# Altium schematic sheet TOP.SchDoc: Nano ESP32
size A3; Author: Silvio Navaretti; Revision: V0.3; SheetNumber: 1; SheetTotal: 1; RevAuthor: Silvio Navaretti
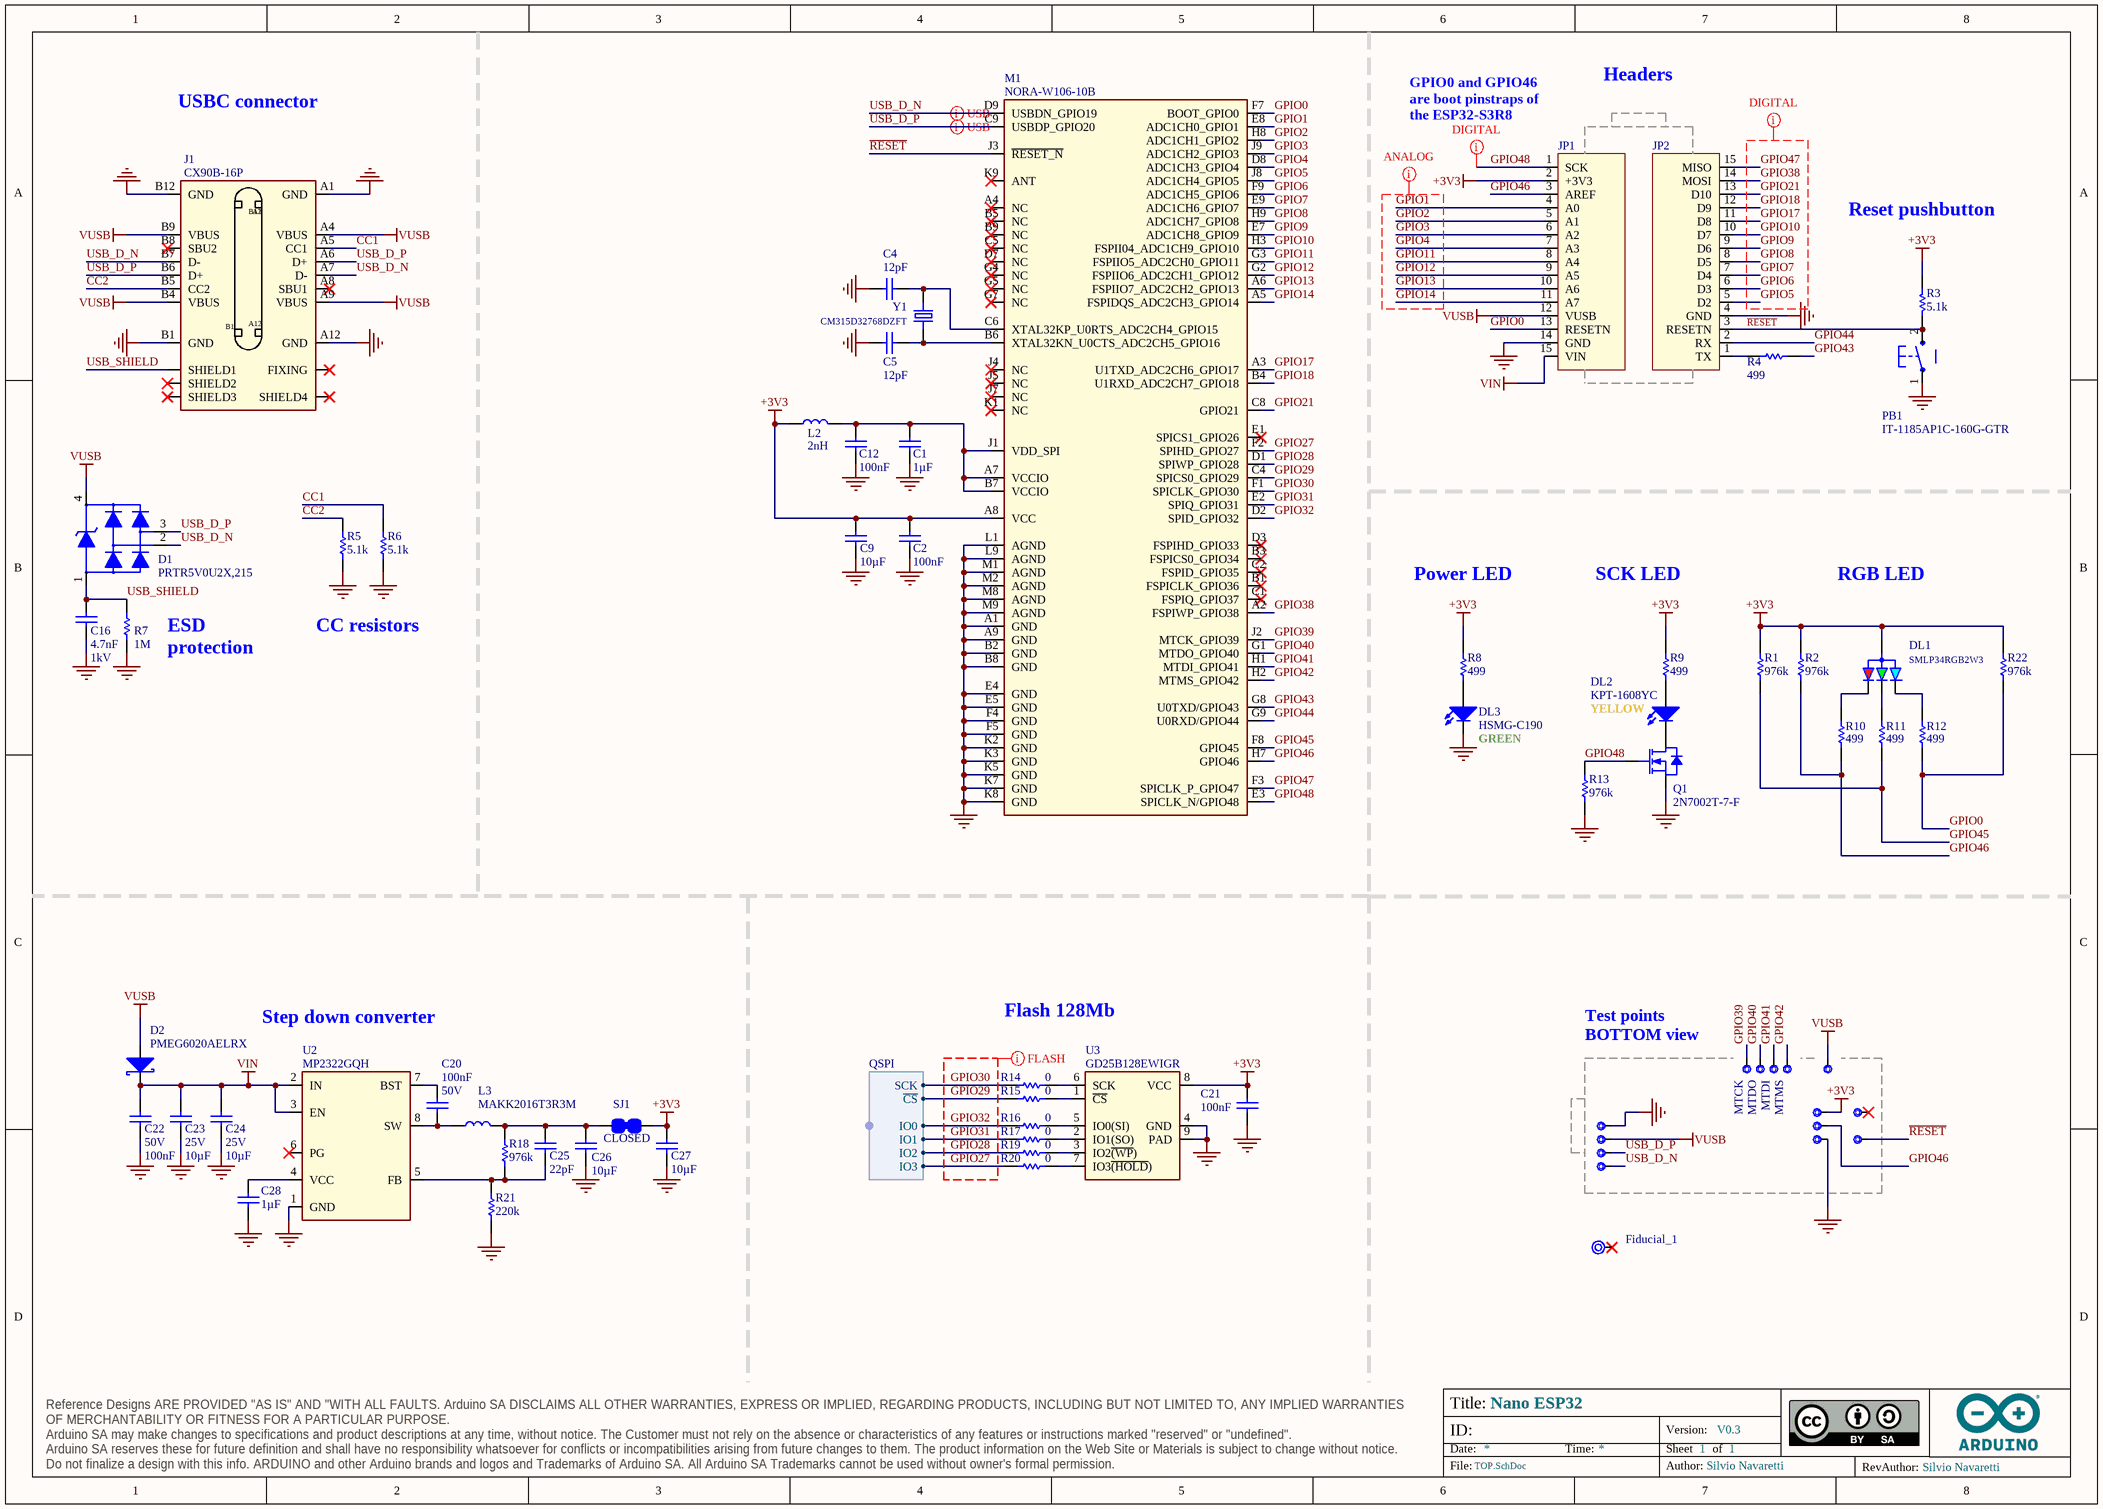
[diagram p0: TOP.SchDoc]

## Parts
3V3  CMP-018-0005-A.3  [TP-1.00MM]  (value not drawn)  (no BOM)
C1  value 1µF  [CAP-0201]  (hidden comment: GRM033R60J105MEA2D)
C2  value 100nF  [CAP-0402]  (hidden comment: GRM155R61H104KE19D)
C4  value 12pF  [CAP-0201]  (hidden comment: GRM0335C1E120JA01J)
C5  value 12pF  [CAP-0201]  (hidden comment: GRM0335C1E120JA01J)
C9  value 10µF  [CAP-0603]  (hidden comment: GRM188R61E106MA73J)
C12  value 100nF  [CAP-0402]  (hidden comment: GRM155R61H104KE19D)
C16  value 4.7nF  Voltage: 1kV  [CAP-0805]  (hidden comment: C0805C472KDRACTU)
C20  value 100nF  Voltage: 50V  [CAP-0402]  (hidden comment: GRM155R61H104KE19D)
C21  value 100nF  [CAP-0402]  (hidden comment: GRM155R61H104KE19D)
C22  value 100nF  Voltage: 50V  [CAP-0402]  (hidden comment: GRM155R61H104KE19D)
C23  value 10µF  Voltage: 25V  [CAP-0603]  (hidden comment: GRM188R61E106MA73J)
C24  value 10µF  Voltage: 25V  [CAP-0603]  (hidden comment: GRM188R61E106MA73J)
C25  value 22pF  [CAP-0402]  (hidden comment: C0402C220J5GAC7411)
C26  value 10µF  [CAP-0603]  (hidden comment: GRM188R61E106MA73J)
C27  value 10µF  [CAP-0603]  (hidden comment: GRM188R61E106MA73J)
C28  value 1µF  [CAP-0201]  (hidden comment: GRM033R60J105MEA2D)
D1  PRTR5V0U2X,215  [SOT190P230X110-4N]
D2  PMEG6020AELRX  [SOD123-1]
D+1  CMP-018-0005-A.3  [TP-1.00MM]  (value not drawn)  (no BOM)
D-1  CMP-018-0005-A.3  [TP-1.00MM]  (value not drawn)  (no BOM)
DL1  SMLP34RGB2W3  [SMLP34RGB2W]
DL2  KPT-1608YC  [LEDC1608X80N-AK]
DL3  HSMG-C190  [LEDC1608X80N-AK]
Fiducial_1  Fiducial mark 1mm with 2mm solder  [Fiducial mark 1mm with circle-Footprint-1]  (value not drawn)  (no BOM)
GND1  CMP-018-0005-A.3  [TP-1.00MM]  (value not drawn)  (no BOM)
GND2  CMP-018-0005-A.3  [TP-1.00MM]  (value not drawn)  (no BOM)
GPIO46  CMP-018-0005-A.3  [TP-1.00MM]  (value not drawn)  (no BOM)
J1  CX90B-16P  [CX90B-16P-Footprint-1]
JP1  PINHD-1X15-NANO-ANALOG-CASTELLATED  [PINHD-1X14_5VF]  (value not drawn)
JP2  PINHD-1X15-NANO-DIGITAL-CASTELLATED  [PINHD-1X14_5VF]  (value not drawn)
L2  Inductance: 2nH  [L-0402]  (hidden comment: BSCH001005052N0SCP)
L3  MAKK2016T3R3M  [MAKK2016T3R3M-Footprint-1]
M1  NORA-W106-10B  [NORA-W106-Footprint-1]
MTCK  CMP-018-0005-A.3  [TP-1.00MM]  (value not drawn)  (no BOM)
MTDI  CMP-018-0005-A.3  [TP-1.00MM]  (value not drawn)  (no BOM)
MTDO  CMP-018-0005-A.3  [TP-1.00MM]  (value not drawn)  (no BOM)
MTMS  CMP-018-0005-A.3  [TP-1.00MM]  (value not drawn)  (no BOM)
NC1  CMP-018-0005-A.3  [TP-1.00MM]  (value not drawn)  (no BOM)
NC2  CMP-018-0005-A.3  [TP-1.00MM]  (value not drawn)  (no BOM)
PB1  IT-1185AP1C-160G-GTR  [C&K_PTS820_NO_HOLES-1]
Q1  2N7002T-7-F  [SOT523]
R1  value 976k  [RES-0201]  (hidden comment: RMCF0201FT976K)
R2  value 976k  [RES-0201]  (hidden comment: RMCF0201FT976K)
R3  value 5.1k  [RES-0201]  (hidden comment: RC0201FR-075K1L)
R4  value 499  [RES-0201]  (hidden comment: CRCW0201499RFKED)
R5  value 5.1k  [RES-0201]  (hidden comment: RC0201FR-075K1L)
R6  value 5.1k  [RES-0201]  (hidden comment: RC0201FR-075K1L)
R7  value 1M  [RES-0402]  (hidden comment: CRCW04021M00FKED)
R8  value 499  [RES-0201]  (hidden comment: CRCW0201499RFKED)
R9  value 499  [RES-0201]  (hidden comment: CRCW0201499RFKED)
R10  value 499  [RES-0201]  (hidden comment: CRCW0201499RFKED)
R11  value 499  [RES-0201]  (hidden comment: CRCW0201499RFKED)
R12  value 499  [RES-0201]  (hidden comment: CRCW0201499RFKED)
R13  value 976k  [RES-0201]  (hidden comment: RMCF0201FT976K)
R14  value 0  [RES-0201]  (hidden comment: CRCW02010000Z0ED)
R15  value 0  [RES-0201]  (hidden comment: CRCW02010000Z0ED)
R16  value 0  [RES-0201]  (hidden comment: CRCW02010000Z0ED)
R17  value 0  [RES-0201]  (hidden comment: CRCW02010000Z0ED)
R18  value 976k  [RES-0201]  (hidden comment: RMCF0201FT976K)
R19  value 0  [RES-0201]  (hidden comment: CRCW02010000Z0ED)
R20  value 0  [RES-0201]  (hidden comment: CRCW02010000Z0ED)
R21  value 220k  [RES-0201]  (hidden comment: AC0201FR-07220KL)
R22  value 976k  [RES-0201]  (hidden comment: RMCF0201FT976K)
SJ1  SMD solder JUMPER CLOSED  [SJ]  (value not drawn)  (no BOM)
TP_VUSB  CMP-018-0005-A.3  [TP-1.00MM]  (value not drawn)  (no BOM)
U2  MP2322GQH  [QFN50P150X200X90-8L]
U3  GD25B128EWIGR  [PSON127P600X60_HS-9N]
VUSB  CMP-018-0005-A.3  [TP-1.00MM]  (value not drawn)  (no BOM)
Y1  CM315D32768DZFT  [ABS07]

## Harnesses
QSPI: SCK, ~{CS}, IO0, IO1, IO2, IO3

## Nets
+3V3: 3V3.X C2.2 C9.2 C21.2 C27.2 DL1.1(ANODE) JP1.2(+3V3) L2.1 M1.A8(VCC) R1.2 R2.2 R3.2 R8.2 R9.2 R22.2 SJ1.2 U3.8(VCC)
GND: C1.1 C2.1 C4.2 C5.2 C9.1 C12.1 C16.1 C21.1 C22.2 C23.1 C24.1 C26.1 C27.1 C28.1 DL3.C GND1.X GND2.X J1.A1(GND) J1.A12(GND) J1.B1(GND) J1.B12(GND) JP1.14(GND) JP2.4(GND) M1.A1(GND) M1.A9(GND) M1.B2(GND) M1.B8(GND) M1.E4(GND) M1.E5(GND) M1.F4(GND) M1.F5(GND) M1.K2(GND) M1.K3(GND) M1.K5(GND) M1.K7(GND) M1.K8(GND) M1.L1(AGND) M1.L9(AGND) M1.M1(AGND) M1.M2(AGND) M1.M8(AGND) M1.M9(AGND) PB1.1 Q1.S R5.1 R6.1 R7.1 R13.1 R21.1 U2.1(GND) U3.4(GND) U3.9(PAD)
VIN: C22.1 C23.2 C24.2 D2.C JP1.15(VIN) U2.2(IN) U2.3(EN)
VUSB: D1.4 D2.A J1.A4(VBUS) J1.A9(VBUS) J1.B4(VBUS) J1.B9(VBUS) JP1.12(VUSB) TP_VUSB.X VUSB.X
CC1: J1.A5(CC1) R6.2
CC2: J1.B5(CC2) R5.2
GPIO0: JP1.13(RESETN) M1.F7(BOOT_GPIO0) R12.1 R22.1
GPIO1: JP1.4(A0) M1.E8(ADC1CH0_GPIO1)
GPIO2: JP1.5(A1) M1.H8(ADC1CH1_GPIO2)
GPIO3: JP1.6(A2) M1.J9(ADC1CH2_GPIO3)
GPIO4: JP1.7(A3) M1.D8(ADC1CH3_GPIO4)
GPIO5: JP2.5(D2) M1.J8(ADC1CH4_GPIO5)
GPIO6: JP2.6(D3) M1.F9(ADC1CH5_GPIO6)
GPIO7: JP2.7(D4) M1.E9(ADC1CH6_GPIO7)
GPIO8: JP2.8(D5) M1.H9(ADC1CH7_GPIO8)
GPIO9: JP2.9(D6) M1.E7(ADC1CH8_GPIO9)
GPIO10: JP2.10(D7) M1.H3(FSPII04_ADC1CH9_GPIO10)
GPIO11: JP1.8(A4) M1.G3(FSPIIO5_ADC2CH0_GPIO11)
GPIO12: JP1.9(A5) M1.G2(FSPIIO6_ADC2CH1_GPIO12)
GPIO13: JP1.10(A6) M1.A6(FSPIIO7_ADC2CH2_GPIO13)
GPIO14: JP1.11(A7) M1.A5(FSPIDQS_ADC2CH3_GPIO14)
GPIO17: JP2.11(D8) M1.A3(U1TXD_ADC2CH6_GPIO17)
GPIO18: JP2.12(D9) M1.B4(U1RXD_ADC2CH7_GPIO18)
GPIO21: JP2.13(D10) M1.C8(GPIO21)
GPIO27: M1.F2(SPIHD_GPIO27) R20.1 ; harness QSPI.IO3
GPIO28: M1.D1(SPIWP_GPIO28) R19.1 ; harness QSPI.IO2
GPIO29: M1.C4(SPICS0_GPIO29) R15.1 ; harness QSPI.~{CS}
GPIO30: M1.F1(SPICLK_GPIO30) R14.1 ; harness QSPI.SCK
GPIO31: M1.E2(SPIQ_GPIO31) R17.1 ; harness QSPI.IO1
GPIO32: M1.D2(SPID_GPIO32) R16.1 ; harness QSPI.IO0
GPIO38: JP2.14(MOSI) M1.A2(FSPIWP_GPIO38)
GPIO39: M1.J2(MTCK_GPIO39) MTCK.X
GPIO40: M1.G1(MTDO_GPIO40) MTDO.X
GPIO41: M1.H1(MTDI_GPIO41) MTDI.X
GPIO42: M1.H2(MTMS_GPIO42) MTMS.X
GPIO43: M1.G8(U0TXD/GPIO43) R4.2
GPIO44: JP2.2(RX) M1.G9(U0RXD/GPIO44)
GPIO45: M1.F8(GPIO45) R1.1 R11.1
GPIO46: GPIO46.X JP1.3(AREF) M1.H7(GPIO46) R2.1 R10.1
GPIO47: JP2.15(MISO) M1.F3(SPICLK_P_GPIO47)
GPIO48: JP1.1(SCK) M1.E3(SPICLK_N/GPIO48) Q1.G R13.2
~{RESET}: JP2.3(RESETN) M1.J3(~{RESET_N}) NC2.X PB1.2 R3.1
USB_D_N: D1.2 D-1.X J1.A7(D-) J1.B7(D-) M1.D9(USBDN_GPIO19)
USB_D_P: D1.3 D+1.X J1.A6(D+) J1.B6(D+) M1.C9(USBDP_GPIO20)
USB_SHIELD: C16.2 D1.1 J1.SHIELD1 R7.2
NetC1_2: C1.2 C12.2 L2.2 M1.A7(VCCIO) M1.B7(VCCIO) M1.J1(VDD_SPI)
NetC4_1: C4.1 M1.C6(XTAL32KP_U0RTS_ADC2CH4_GPIO15) Y1.2
NetC5_1: C5.1 M1.B6(XTAL32KN_U0CTS_ADC2CH5_GPIO16) Y1.1
NetC20_1: C20.1 L3.1 U2.8(SW)
NetC20_2: C20.2 U2.7(BST)
NetC25_1: C25.1 R18.1 R21.2 U2.5(FB)
NetC25_2: C25.2 C26.2 L3.2 R18.2 SJ1.1
NetC28_2: C28.2 U2.4(VCC)
NetDL1_2: DL1.2(RED_C) R10.2
NetDL1_3: DL1.3(BLUE_C) R12.2
NetDL1_4: DL1.4(GREEN_C) R11.2
NetDL2_A: DL2.A R9.1
NetDL2_C: DL2.C Q1.D
NetDL3_A: DL3.A R8.1
NetJP2_1: JP2.1(TX) R4.1
NetR14_2: R14.2 U3.6(SCK)
NetR15_2: R15.2 U3.1(~{CS})
NetR16_2: R16.2 U3.5(IO0(SI))
NetR17_2: R17.2 U3.2(IO1(SO))
NetR19_2: R19.2 U3.3(IO2~{(WP}))
NetR20_2: R20.2 U3.7(IO3~{(HOLD}))

Not connected (* = marked no-connect by the designer): Fiducial_1 1*; J1 A8(SBU1)* B8(SBU2)* FIXING* SHIELD2* SHIELD3* SHIELD4*; M1 A4(NC)* B1(FSPICLK_GPIO36)* B3(FSPICS0_GPIO34)* B5(NC)* B9(NC)* C1(FSPIQ_GPIO37)* C2(FSPID_GPIO35)* C5(NC)* D3(FSPIHD_GPIO33)* D7(NC)* E1(SPICS1_GPIO26)* G4(NC)* G5(NC)* G7(NC)* J4(NC)* J5(NC)* J7(NC)* K1(NC)* K9(ANT)*; NC1 X*; U2 6(PG)*

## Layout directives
differential pair; differential pair class USB: USB_D_N, USB_D_P
net class FLASH: GPIO27, GPIO28, GPIO29, GPIO30, GPIO31, GPIO32
net class ANALOG: GPIO1, GPIO2, GPIO3, GPIO4, GPIO11, GPIO12, GPIO13, GPIO14
net class DIGITAL: GPIO5, GPIO6, GPIO7, GPIO8, GPIO9, GPIO10, GPIO17, GPIO18, GPIO21, GPIO38, GPIO47, GPIO48

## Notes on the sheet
- USBC connector
- Headers
- (near JP1) GPIO0 and GPIO46 are boot pinstraps of the ESP32-S3R8
- Reset pushbutton
- Power LED
- SCK LED
- RGB LED
- ESD
  protection
- CC resistors
- YELLOW
- (near DL3) GREEN
- Step down converter
- Flash 128Mb
- Test points BOTTOM view

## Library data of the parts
3V3 D+1 D-1 GND1 GND2 GPIO46 MTCK MTDI MTDO MTMS NC1 NC2 TP_VUSB VUSB = UT0013-A.4: Test point 1.00mm
C1 C28 = C0002-A.12: CAP CHIP 0201 1uF 6.3V X5R 20%; Manufacturer: Murata; Code Arduino: A5520
C2 C12 C20-C22 = C0015-A.11: CAP CHIP 0402 100nF 50V X5R 10%; Manufacturer: Murata; Code Arduino: A5141
C4 C5 = C0003-A.12: CAP CHIP 0201 12pF 25V C0G 5%; Manufacturer: Murata; Code Arduino: C0003
C9 C23 C24 C26 C27 = C0047-A.15: CAP CHIP 0603 10uF 25V X5R 20%; Manufacturer: Murata; Code Arduino: 2213
C16 = C0059-A.11: CAP CHIP 0805 4.7nF 1000V X7R 10%; Manufacturer: KEMET; Code Arduino: 0689
C25 = C0029-A.11: CAP CHIP 0402 22pF 50V C0G 5%; Manufacturer: KEMET; Code Arduino: 0137
D1 = D0025-A.5: TVS ARRAY 4LIN.8kV 1pF SOT143B; Manufacturer: Nexperia; Device Type: ESD protection; Code Arduino: 2209
D2 = D0026-A.6: DIODE SCHOTTKY SMD 2A 60V SOD123FL; Manufacturer: Nexperia; Manucturer Part Number 2: SS26L; Code Arduino: 2208; Forward Voltage: 0.6V; Manucturer 2: Hottech
DL1 = L0014-A.10: LED RGB DIFFUSED PICOLED SMD; Manufacturer: ROHM Semiconductor; Code Arduino: A5469; Forward Current: 20mA; Lens Style: Rectangular; Dominant Wavelength: 470nm; Forward Voltage: 3V; Test Current: 5mA; Luminous Intensity: 45mcd; Lens Color: White
DL2 = L0008-A.4: LED SMD 0603 GIA588   8mcd 120^; Manufacturer: Kingbright; Code Arduino: 2243
DL3 = L0009-A.4: LED SMD 0603 GREEN/568 15mcd 120^; Manufacturer: Broadcom; Code Arduino: 2204
Fiducial_1 = UT0024-A.6
J1 = J0272-A.3: CONN RCPT USB3.1 TYPEC 16POS SMD; Manufacturer: Hirose; Code Arduino: J0272
JP1 = J0158-A.2: CONN THD SOCKET F/1/D 15V JANALOG NANO-TYPE CASTELLATED; Code Arduino: A5563
JP2 = J0183-A.1: CONN THD SOCKET F/1/D 15V JDIGITAL NANO-TYPE CASTELLATED; Code Arduino: A5564
L2 = I0069-A.3: IND CHIP 0402 2nH +-0.3nH 400mA; Manufacturer: Pulse Electronics; Code Arduino: I0069; Series Resistance: 100mR; Test Frequency: 100MHz; Frequency: 8.1GHz; DC Resistance (DCR): 100m
L3 = I0045-A.9: IND CHIP 0806 3.3 uH 20% 1.2A; Manufacturer: Taiyo Yuden; Max DC Current: 1.15A; Core Material: Metal; DC Resistance (DCR): 255mR; Code Arduino: I0045; Test Frequency: 2MHz; Inductance: 3.3µH; Shielding: Shielded; Value: 3.3µH
M1 = M0028-A.9: MODULE WIFI +BLE5 ESP32-S3; Manufacturer: U-Blox; Code Arduino: M0028
PB1 = B0001-A.7: PUSHBUTTON WHITE NO ANCHORS; Manufacturer: Switronic; Code Arduino: 0173
Q1 = T0003-A.2: MOSFET N-CH 60V 115mA SOT523; Manufacturer: Diodes Inc.; Device Type: Mosfet N-CH SMD; Code Arduino: 2368
R1 R2 R13 R18 R22 = R0198-A.11: RES CHIP 0201 976k 1/20W 1%; Manufacturer: Stackpole Electronics Inc; Power: 50mW; Code Arduino: R0198
R3 = R0169-A.15: RES CHIP 0201 5.1k OHM 1/20W 1%; Manufacturer: Yageo; Code Arduino: R0169; Power: 50mW; Resistance: 5.1kR; Voltage Rating: 25V; Temperature Coefficient: 200ppm/°C
R4 = R0185-A.13: RES CHIP 0201 499R 1/20W 1%; Manufacturer: Vishay; Power: 50mW; Voltage Rating (DC): 30V; Code Arduino: R0185; Temperature Coefficient: 100ppm/°C
R5 R6 = R0169-A.15: RES CHIP 0201 5.1k OHM 1/20W 1%; Manufacturer: Yageo; Power: 50mW; Code Arduino: R0169; Resistance: 5.1kR; Voltage Rating: 25V; Temperature Coefficient: 200ppm/°C
R7 = R0058-A.15: RES CHIP 0402 1M 1% 1/16W; Manufacturer: Vishay; Power: 63mW; Code Arduino: 0139
R8 R9 = R0185-A.13: RES CHIP 0201 499R 1/20W 1%; Manufacturer: Vishay; Code Arduino: R0185; Power: 50mW; Voltage Rating (DC): 30V; Temperature Coefficient: 100ppm/°C
R10-R12 = R0185-A.13: RES CHIP 0201 499R 1/20W 1%; Manufacturer: Vishay; Power: 50mW; Code Arduino: R0185; Voltage Rating (DC): 30V; Temperature Coefficient: 100ppm/°C
R14-R17 R19 R20 = R0140-A.13: RES CHIP 0201 0R 1/20W 5%; Manufacturer: Vishay; Code Arduino: R0140; Power: 50mW
R21 = R0199-A.11: RES CHIP 0201 220k 1% 1/20W; Manufacturer: Yageo; Code Arduino: R0199; Power: 50mW
SJ1 = UT0006-A.12: Solder Jumper shorted pads. This is not a component
U2 = U0072-A.6: IC STEP DOWN CONV 1A 22V QFN8; Manufacturer: Monolithic Power Systems; Code Arduino: U0072
U3 = U0297-A.2: IC FLASH 128MB 6DFN 3V; Manufacturer: Giga Devices; Code Arduino: U0297; Max Supply Voltage: 3.6V
Y1 = X0003-A.5: CRYSTAL 32.768kHz 20ppm 12.5pF SMD 1.6x0.9mm; Manufacturer: Citizen FineDevice; Series Resistance: 70kR; Code Arduino: 0213; Frequency Stability: 0.12%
